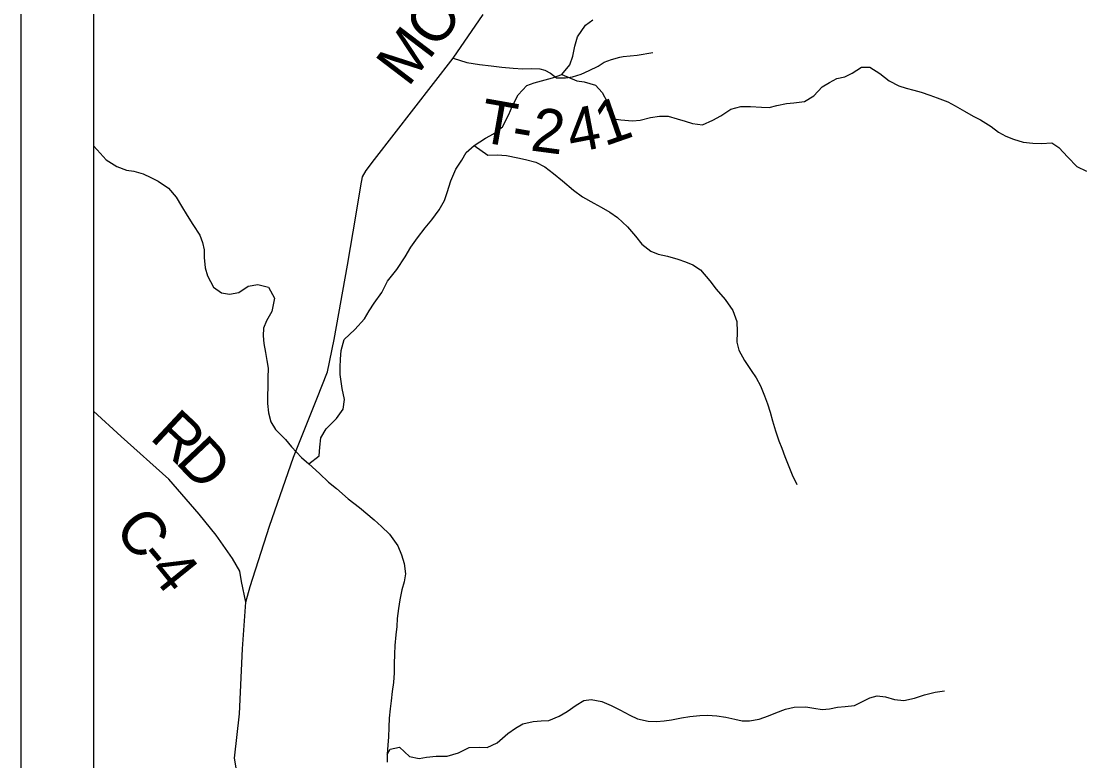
# Model space of a CAD drawing. Extents: x 0 to 34, y 0 to 22.
# Drawn here: x 2.106 to 3.486, y 15.799 to 16.76 of the extents above; entities that cross this region are included whole.
import ezdxf

# ---------------------------------------------------------------- set-up
doc = ezdxf.new("R2010")
doc.units = 0
for name, color, linetype in [('Default', 7, 'Continuous'), ('GM_X_County_Road', 7, 'Continuous'), ('GM_X_County_Road_Text', 7, 'Continuous'), ('GM_X_Minor_River', 7, 'Continuous'), ('GM_X_Township_Road', 7, 'Continuous'), ('GM_X_Township_Road_Text', 7, 'Continuous'), ('SH_Cut_Line', 7, 'Continuous')]:
    doc.layers.add(name, color=color, linetype=linetype)

msp = doc.modelspace()

# ---------------------------------------------------------------- linework, layer by layer
at = {"layer": 'Default'}
msp.add_lwpolyline([(9.087, 13.8822), (2.1062, 13.8822), (2.1062, 20.9054), (9.087, 20.9054)], close=True, dxfattribs=at)
msp.add_lwpolyline([(2.2, 19.4329), (2.2, 14), (4.485, 14)], dxfattribs=at)
at = {"layer": 'GM_X_County_Road'}
for points in [[(2.3981, 16.0051), (2.404, 16.0255), (2.429, 16.1038), (2.4603, 16.1935), (2.4906, 16.2694), (2.5042, 16.3046), (2.513, 16.3466), (2.5303, 16.4432), (2.5416, 16.5092), (2.5476, 16.5463), (2.55, 16.558), (2.5547, 16.5663), (2.5654, 16.5806), (2.6678, 16.712), (2.7066, 16.7689)], [(2.3981, 16.0051), (2.3927, 16.0321), (2.3902, 16.0454), (2.3809, 16.0618), (2.3597, 16.0921), (2.3377, 16.1197), (2.2981, 16.1649), (2.2363, 16.2206), (2.2, 16.2533)], [(2.3966, 15.7268), (2.3834, 15.8025), (2.3901, 15.8598), (2.3937, 15.9444), (2.3981, 16.0051)]]:
    msp.add_lwpolyline(points, dxfattribs=at)
at = {"layer": 'GM_X_Minor_River'}
for points in [[(2.4799, 16.1849), (2.4935, 16.1954), (2.4943, 16.2064), (2.4955, 16.2185), (2.5024, 16.2306), (2.5161, 16.2438), (2.5245, 16.2559), (2.5264, 16.2684), (2.5235, 16.2828), (2.5209, 16.3011), (2.5206, 16.3106), (2.5211, 16.3208), (2.5219, 16.3322), (2.5261, 16.3466), (2.5398, 16.3594), (2.5524, 16.3734), (2.5585, 16.3836), (2.565, 16.3938), (2.5749, 16.4077), (2.5822, 16.4225), (2.5944, 16.4376), (2.6051, 16.4539), (2.6127, 16.4667), (2.6215, 16.4788), (2.6314, 16.4916), (2.6398, 16.5022), (2.6493, 16.515), (2.6565, 16.5271), (2.66, 16.5377), (2.6646, 16.5529), (2.6712, 16.568), (2.6788, 16.5794), (2.6845, 16.5896), (2.6952, 16.5986), (2.7096, 16.6084), (2.7202, 16.614), (2.732, 16.6231), (2.74, 16.6389), (2.7446, 16.6495), (2.7523, 16.6647), (2.7633, 16.6767), (2.7732, 16.6801), (2.7872, 16.6842), (2.797, 16.6868), (2.8091, 16.6909), (2.8194, 16.7037), (2.8233, 16.7147), (2.826, 16.7276), (2.8291, 16.7397), (2.8398, 16.7552), (2.8493, 16.762)], [(2.8091, 16.6909), (2.8283, 16.6829), (2.8381, 16.6814), (2.8526, 16.6772), (2.8613, 16.6677), (2.8677, 16.6552), (2.8677, 16.6457), (2.8738, 16.6339), (2.8855, 16.632), (2.9007, 16.6309), (2.9106, 16.6316), (2.9242, 16.635), (2.936, 16.6369), (2.947, 16.6369), (2.9587, 16.6335), (2.9693, 16.6301), (2.9788, 16.6271), (2.9917, 16.6255), (3.0054, 16.6316), (3.0156, 16.6373), (3.0285, 16.6457), (3.0418, 16.6495), (3.0543, 16.6495), (3.0687, 16.6483), (3.0786, 16.648), (3.0884, 16.6506), (3.1009, 16.6533), (3.1104, 16.654), (3.1245, 16.6559), (3.1366, 16.6632), (3.1472, 16.675), (3.1567, 16.6807), (3.1662, 16.6856), (3.1768, 16.6879), (3.1863, 16.6928), (3.1984, 16.7004), (3.2091, 16.7004), (3.2223, 16.6921), (3.2345, 16.6829), (3.247, 16.6761), (3.2565, 16.6731), (3.2663, 16.6704), (3.2762, 16.6681), (3.2872, 16.6639), (3.297, 16.6605), (3.3107, 16.6552), (3.3202, 16.6502), (3.3323, 16.6434), (3.3437, 16.6369), (3.3531, 16.632), (3.3672, 16.6232), (3.3766, 16.616), (3.3861, 16.6107), (3.396, 16.6069), (3.4085, 16.6031), (3.421, 16.6016), (3.4324, 16.6012), (3.4457, 16.602), (3.4551, 16.5959), (3.4665, 16.5833), (3.4783, 16.5712), (3.4908, 16.5651)], [(2.2, 16.5982), (2.2051, 16.5932), (2.2165, 16.5799), (2.2305, 16.5712), (2.243, 16.5666), (2.2525, 16.5651), (2.2646, 16.5617), (2.2749, 16.5571), (2.2844, 16.5522), (2.2976, 16.5434), (2.3075, 16.5316), (2.3147, 16.5198), (2.3219, 16.5077), (2.3295, 16.4959), (2.3382, 16.4822), (2.342, 16.4727), (2.3439, 16.4632), (2.3442, 16.4529), (2.3454, 16.4396), (2.3484, 16.4294), (2.356, 16.4145), (2.3666, 16.4073), (2.3768, 16.4054), (2.3893, 16.4077), (2.4011, 16.4157), (2.414, 16.4179), (2.4276, 16.4145), (2.4356, 16.4001), (2.4322, 16.383), (2.425, 16.3708), (2.4212, 16.3613), (2.4208, 16.3514), (2.4215, 16.3415), (2.4238, 16.3294), (2.4257, 16.3191), (2.4272, 16.3092), (2.4268, 16.2967), (2.4268, 16.2841), (2.4264, 16.2742), (2.4264, 16.2632), (2.4276, 16.2514), (2.4306, 16.2396), (2.4367, 16.2294), (2.4499, 16.2164), (2.4575, 16.2069), (2.4704, 16.1932), (2.4799, 16.1849), (2.4939, 16.1723), (2.5056, 16.1609), (2.5159, 16.1529)], [(2.6952, 16.5986), (2.7129, 16.586), (2.7247, 16.5864), (2.7372, 16.5856), (2.7516, 16.5826), (2.7619, 16.5803), (2.7751, 16.5769), (2.7869, 16.5708), (2.7983, 16.5624), (2.81, 16.5529), (2.824, 16.5407), (2.8358, 16.532), (2.8506, 16.5236), (2.8601, 16.5187), (2.8714, 16.5119), (2.8813, 16.505), (2.8942, 16.4928), (2.9048, 16.4807), (2.9131, 16.4704), (2.9245, 16.4613), (2.934, 16.4575), (2.9465, 16.4548), (2.9598, 16.451), (2.9696, 16.4476), (2.9791, 16.4434), (2.989, 16.437), (3.0015, 16.4229), (3.0094, 16.4119), (3.0212, 16.3986), (3.0314, 16.3841), (3.0363, 16.3697), (3.0367, 16.3564), (3.0363, 16.343), (3.039, 16.3328), (3.0462, 16.3191), (3.0552, 16.3062), (3.0617, 16.2967), (3.067, 16.2864), (3.0723, 16.2731), (3.0761, 16.2628), (3.0799, 16.2522), (3.0829, 16.2408), (3.0867, 16.2279), (3.0912, 16.2149), (3.095, 16.2054), (3.0988, 16.1944), (3.103, 16.1837), (3.1083, 16.1704), (3.1143, 16.1579)], [(2.5159, 16.1529), (2.531, 16.1396), (2.5458, 16.1282), (2.5648, 16.1123), (2.5746, 16.1035), (2.5849, 16.0933), (2.5959, 16.0784), (2.6004, 16.0666), (2.6042, 16.0552), (2.6057, 16.0419), (2.6042, 16.0317), (2.6011, 16.021), (2.5985, 16.0081), (2.5966, 15.9967), (2.595, 15.9841), (2.5943, 15.9735), (2.5931, 15.9628), (2.592, 15.9488), (2.5916, 15.9374), (2.5912, 15.9248), (2.5908, 15.9134), (2.5901, 15.9009), (2.5886, 15.8891), (2.587, 15.8769), (2.5859, 15.8663), (2.5847, 15.8545), (2.584, 15.8427), (2.5836, 15.8298), (2.5828, 15.8199), (2.5821, 15.8073), (2.5817, 15.7971)], [(2.5821, 15.8073), (2.5859, 15.8142), (2.598, 15.8165), (2.6109, 15.8047), (2.6234, 15.802), (2.6329, 15.8035), (2.6458, 15.8051), (2.6598, 15.8051), (2.6746, 15.8092), (2.6886, 15.8161), (2.7019, 15.8165), (2.7118, 15.8161), (2.725, 15.8222), (2.7387, 15.8343), (2.7486, 15.8412), (2.7584, 15.8469), (2.7717, 15.8499), (2.7823, 15.8507), (2.7922, 15.8515), (2.8055, 15.8568), (2.8157, 15.8632), (2.8275, 15.8712), (2.8377, 15.8773), (2.8472, 15.8788), (2.8608, 15.8758), (2.873, 15.8708), (2.8843, 15.8651), (2.8972, 15.8583), (2.9075, 15.8537), (2.9211, 15.8503), (2.9321, 15.8499), (2.942, 15.8511), (2.9515, 15.8522), (2.9644, 15.8549), (2.9754, 15.8564), (2.9883, 15.8579), (2.9985, 15.8583), (3.0103, 15.8575), (3.022, 15.8556), (3.0338, 15.853), (3.0432, 15.8511), (3.0527, 15.8507), (3.0656, 15.853), (3.0778, 15.8575), (3.0872, 15.8613), (3.0998, 15.8659), (3.1108, 15.8686), (3.1259, 15.8689), (3.1365, 15.8674), (3.1472, 15.8655), (3.157, 15.8663), (3.1673, 15.8686), (3.1771, 15.8697), (3.1893, 15.8709), (3.1999, 15.8758), (3.2094, 15.8807), (3.2189, 15.8834), (3.2295, 15.8819), (3.2412, 15.8788), (3.2537, 15.8773), (3.2674, 15.8804), (3.2803, 15.8845), (3.2943, 15.8883), (3.3065, 15.8899)]]:
    msp.add_lwpolyline(points, dxfattribs=at)
at = {"layer": 'GM_X_Township_Road'}
for points in [[(2.6678, 16.712), (2.6855, 16.7065), (2.7021, 16.704), (2.7169, 16.702), (2.7308, 16.7003), (2.7459, 16.699), (2.7584, 16.6985), (2.769, 16.6987), (2.7803, 16.6982), (2.7867, 16.6966), (2.7943, 16.6928), (2.8018, 16.6866), (2.8135, 16.6865), (2.8226, 16.6879), (2.834, 16.6912), (2.8446, 16.696), (2.856, 16.7016), (2.864, 16.7068), (2.8735, 16.7105), (2.8845, 16.7134), (2.8887, 16.7145), (2.8977, 16.7153)], [(2.8977, 16.7153), (2.9068, 16.7162), (2.9273, 16.7194)]]:
    msp.add_lwpolyline(points, dxfattribs=at)
at = {"layer": 'SH_Cut_Line'}
msp.add_lwpolyline([(2.2, 19.4329), (2.2, 14), (9, 14), (9, 18.8941), (8.8762, 18.9027), (8.0305, 18.9725), (6.8442, 19.0679), (6.226, 19.1161), (5.8337, 19.1499), (5.3224, 19.1939), (5.1554, 19.2083), (4.831, 19.2363), (4.7641, 19.2419), (3.1893, 19.3592), (2.7961, 19.3885)], close=True, dxfattribs=at)

# ---------------------------------------------------------------- texts
at = {"layer": 'GM_X_County_Road_Text'}
for s, rotation, p in [('O', 52.717, (2.6465, 16.7224)), ('M', 52.7195, (2.6092, 16.6734)), ('R', 316.9654, (2.2719, 16.2181)), ('D', 313.3718, (2.3054, 16.1869)), ('C', 310.1784, (2.2253, 16.0983)), ('-', 309.9375, (2.2554, 16.0627)), ('4', 308.9061, (2.2702, 16.0451))]:
    msp.add_text(s, height=0.0568, rotation=rotation, dxfattribs=at).set_placement(p)
at = {"layer": 'GM_X_Township_Road_Text'}
for s, rotation, p in [('T', 350.0156, (2.6994, 16.6041)), ('1', 19.1843, (2.8644, 16.5973)), ('2', 352.4325, (2.7669, 16.5924)), ('4', 10.8678, (2.8214, 16.5884)), ('-', 350.2934, (2.7416, 16.5967))]:
    msp.add_text(s, height=0.0568, rotation=rotation, dxfattribs=at).set_placement(p)

doc.saveas('drawing.dxf')
